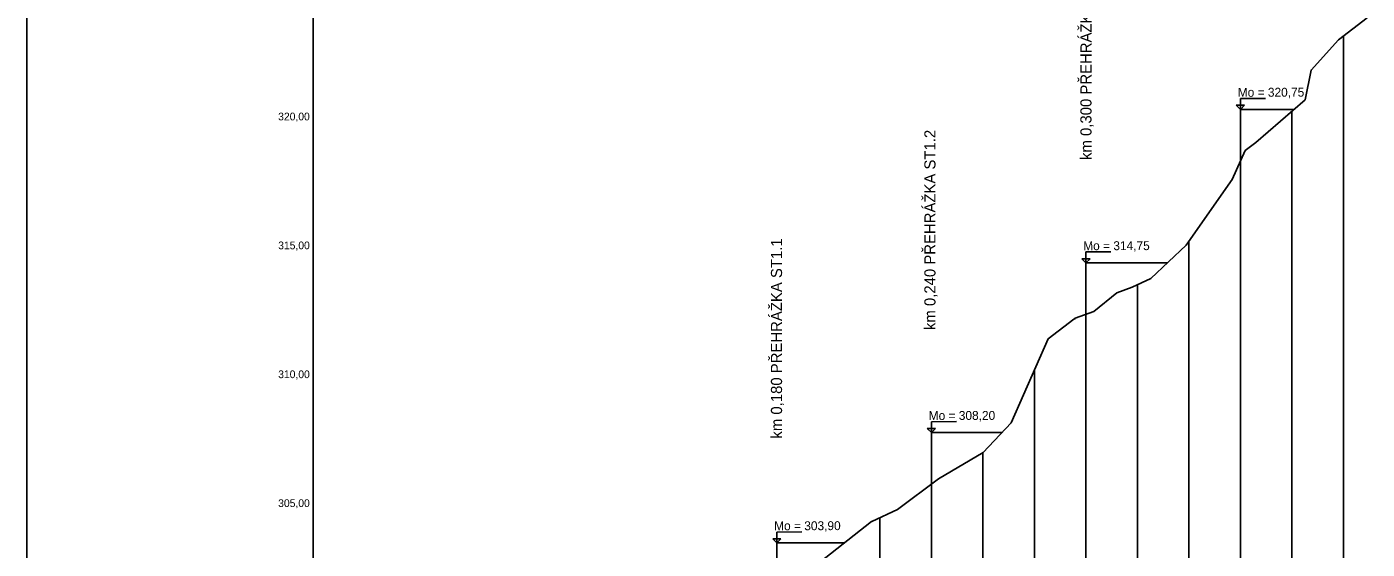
# Model space of a CAD drawing. Extents: x -500244 to -499404, y -1136557 to -1135632.
# Drawn here: x -500244 to -499723, y -1136169 to -1135966 of the extents above; entities that cross this region are included whole.
import ezdxf

# ---------------------------------------------------------------- set-up
doc = ezdxf.new("R2010")
doc.units = 0
for name, color, linetype in [('03_PC_NÁVRH_AS_H', 7, 'Continuous'), ('13', 7, 'Continuous'), ('56', 7, 'Continuous'), ('hraniceABH', 7, 'Continuous'), ('Vrstva 1', 7, 'Continuous'), ('Vrstva 4', 7, 'Continuous')]:
    doc.layers.add(name, color=color, linetype=linetype)

msp = doc.modelspace()

# ---------------------------------------------------------------- linework, layer by layer
for points in [[(-499935.91, -1136173.92), (-499915.71, -1136157.99), (-499915.69, -1136157.98), (-499915.65, -1136157.92), (-499915.63, -1136157.97), (-499905.68, -1136153.32), (-499905.68, -1136153.32), (-499889.7, -1136141.52), (-499889.7, -1136141.52), (-499872.38, -1136131.32), (-499872.38, -1136131.32), (-499861.54, -1136119.82), (-499861.54, -1136119.82), (-499847.07, -1136087.12), (-499847.07, -1136087.12), (-499837.1, -1136079.48), (-499836.91, -1136079.5), (-499836.67, -1136079.17), (-499829.39, -1136076.62), (-499829.39, -1136076.62), (-499820.48, -1136069.32), (-499820.48, -1136069.32), (-499814.56, -1136067.12), (-499814.56, -1136067.12), (-499807.24, -1136063.72), (-499807.24, -1136063.72), (-499793.57, -1136050.82), (-499793.57, -1136050.82), (-499775.71, -1136025.32), (-499775.71, -1136025.32), (-499770.61, -1136014.12), (-499770.61, -1136014.12), (-499766.52, -1136011.02), (-499766.52, -1136011.02), (-499747.38, -1135994.42), (-499747.38, -1135994.42), (-499745.04, -1135982.92), (-499745.04, -1135982.92), (-499734.44, -1135971.22), (-499734.44, -1135971.22), (-499723.25, -1135962.62)], [(-499732.45, -1135969.69), (-499732.45, -1136385.42), (-499732.45, -1136395.42), (-499732.45, -1136424.49)], [(-499752.45, -1135998.82), (-499752.45, -1136385.42), (-499752.45, -1136395.42), (-499752.45, -1136424.49)], [(-499772.45, -1136018.17), (-499772.45, -1136385.42), (-499772.45, -1136395.42), (-499772.45, -1136424.49)], [(-499792.45, -1136049.23), (-499792.45, -1136385.42), (-499792.45, -1136395.42), (-499792.45, -1136424.49)], [(-499812.45, -1136066.14), (-499812.45, -1136385.42), (-499812.45, -1136395.42), (-499812.45, -1136424.49)], [(-499832.45, -1136077.69), (-499832.45, -1136385.42), (-499832.45, -1136395.42), (-499832.45, -1136424.49)], [(-499852.45, -1136099.28), (-499852.45, -1136385.42), (-499852.45, -1136395.42), (-499852.45, -1136424.49)], [(-499872.45, -1136131.36), (-499872.45, -1136385.42), (-499872.45, -1136395.42), (-499872.45, -1136424.49)], [(-499892.45, -1136143.55), (-499892.45, -1136385.42), (-499892.45, -1136395.42), (-499892.45, -1136424.49)], [(-499912.45, -1136156.48), (-499912.45, -1136385.42), (-499912.45, -1136395.42), (-499912.45, -1136424.49)]]:
    msp.add_lwpolyline(points)
at = {"layer": '03_PC_NÁVRH_AS_H'}
for p, q in [((-499772.45, -1135998.17), (-499751.7, -1135998.17)), ((-499772.45, -1136018.17), (-499772.45, -1135998.17)), ((-499832.45, -1136057.69), (-499800.85, -1136057.69)), ((-499832.45, -1136077.69), (-499832.45, -1136057.69)), ((-499892.45, -1136123.55), (-499865.06, -1136123.55)), ((-499892.45, -1136143.55), (-499892.45, -1136123.55)), ((-499952.45, -1136166.34), (-499926.29, -1136166.34)), ((-499952.45, -1136186.34), (-499952.45, -1136166.34))]:
    msp.add_line(p, q, dxfattribs=at)
at = {"layer": '56'}
msp.add_line((-500132.45, -1136424.49), (-500132.45, -1135705.42), dxfattribs=at)
at = {"layer": 'hraniceABH'}
msp.add_line((-500243.68, -1136556.57), (-500243.68, -1135665.57), dxfattribs=at)
at = {"layer": 'Vrstva 1'}
for p, q in [((-499772.47, -1135993.94), (-499762.77, -1135993.92)), ((-499772.45, -1135998.17), (-499772.47, -1135993.94)), ((-499772.45, -1135998.17), (-499774.07, -1135996.57)), ((-499774.07, -1135996.57), (-499770.87, -1135996.57)), ((-499832.45, -1136057.69), (-499834.07, -1136056.09)), ((-499834.07, -1136056.09), (-499830.87, -1136056.09)), ((-499832.47, -1136053.46), (-499822.77, -1136053.44)), ((-499832.45, -1136057.69), (-499832.47, -1136053.46)), ((-499892.45, -1136123.55), (-499894.07, -1136121.95)), ((-499894.07, -1136121.95), (-499890.87, -1136121.95)), ((-499892.47, -1136119.32), (-499882.77, -1136119.3)), ((-499892.45, -1136123.55), (-499892.47, -1136119.32)), ((-499952.45, -1136166.34), (-499954.07, -1136164.74)), ((-499954.07, -1136164.74), (-499950.87, -1136164.74)), ((-499952.47, -1136162.11), (-499942.77, -1136162.09)), ((-499952.45, -1136166.34), (-499952.47, -1136162.11))]:
    msp.add_line(p, q, dxfattribs=at)
at = {"layer": 'Vrstva 4'}
for p, q in [((-499770.87, -1135996.57), (-499772.45, -1135998.17)), ((-499830.87, -1136056.09), (-499832.45, -1136057.69)), ((-499890.87, -1136121.95), (-499892.45, -1136123.55)), ((-499950.87, -1136164.74), (-499952.45, -1136166.34))]:
    msp.add_line(p, q, dxfattribs=at)

# ---------------------------------------------------------------- texts
at = {"layer": '13'}
for s, p in [('km 0,300 PŘEHRÁŽKA ST1.3', (-499830.29, -1136017.79)), ('km 0,240 PŘEHRÁŽKA ST1.2', (-499890.87, -1136083.77)), ('km 0,180 PŘEHRÁŽKA ST1.1', (-499950.44, -1136125.88))]:
    msp.add_text(s, height=4.32, rotation=90, dxfattribs=at).set_placement(p)
for s, p in [('320,00', (-500146.07, -1136002.42)), ('315,00', (-500146.07, -1136052.42)), ('310,00', (-500146.07, -1136102.42)), ('305,00', (-500146.07, -1136152.42))]:
    msp.add_text(s, height=3, dxfattribs=at).set_placement(p)
at = {"layer": 'Vrstva 1'}
for s, p in [('Mo = 320,75', (-499773.5, -1135993.27)), ('Mo = 314,75', (-499833.5, -1136052.8)), ('Mo = 308,20', (-499893.5, -1136118.66)), ('Mo = 303,90', (-499953.5, -1136161.44))]:
    msp.add_text(s, height=3.456, rotation=0.1193, dxfattribs=at).set_placement(p)

doc.saveas('drawing.dxf')
